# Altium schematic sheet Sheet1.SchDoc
size B
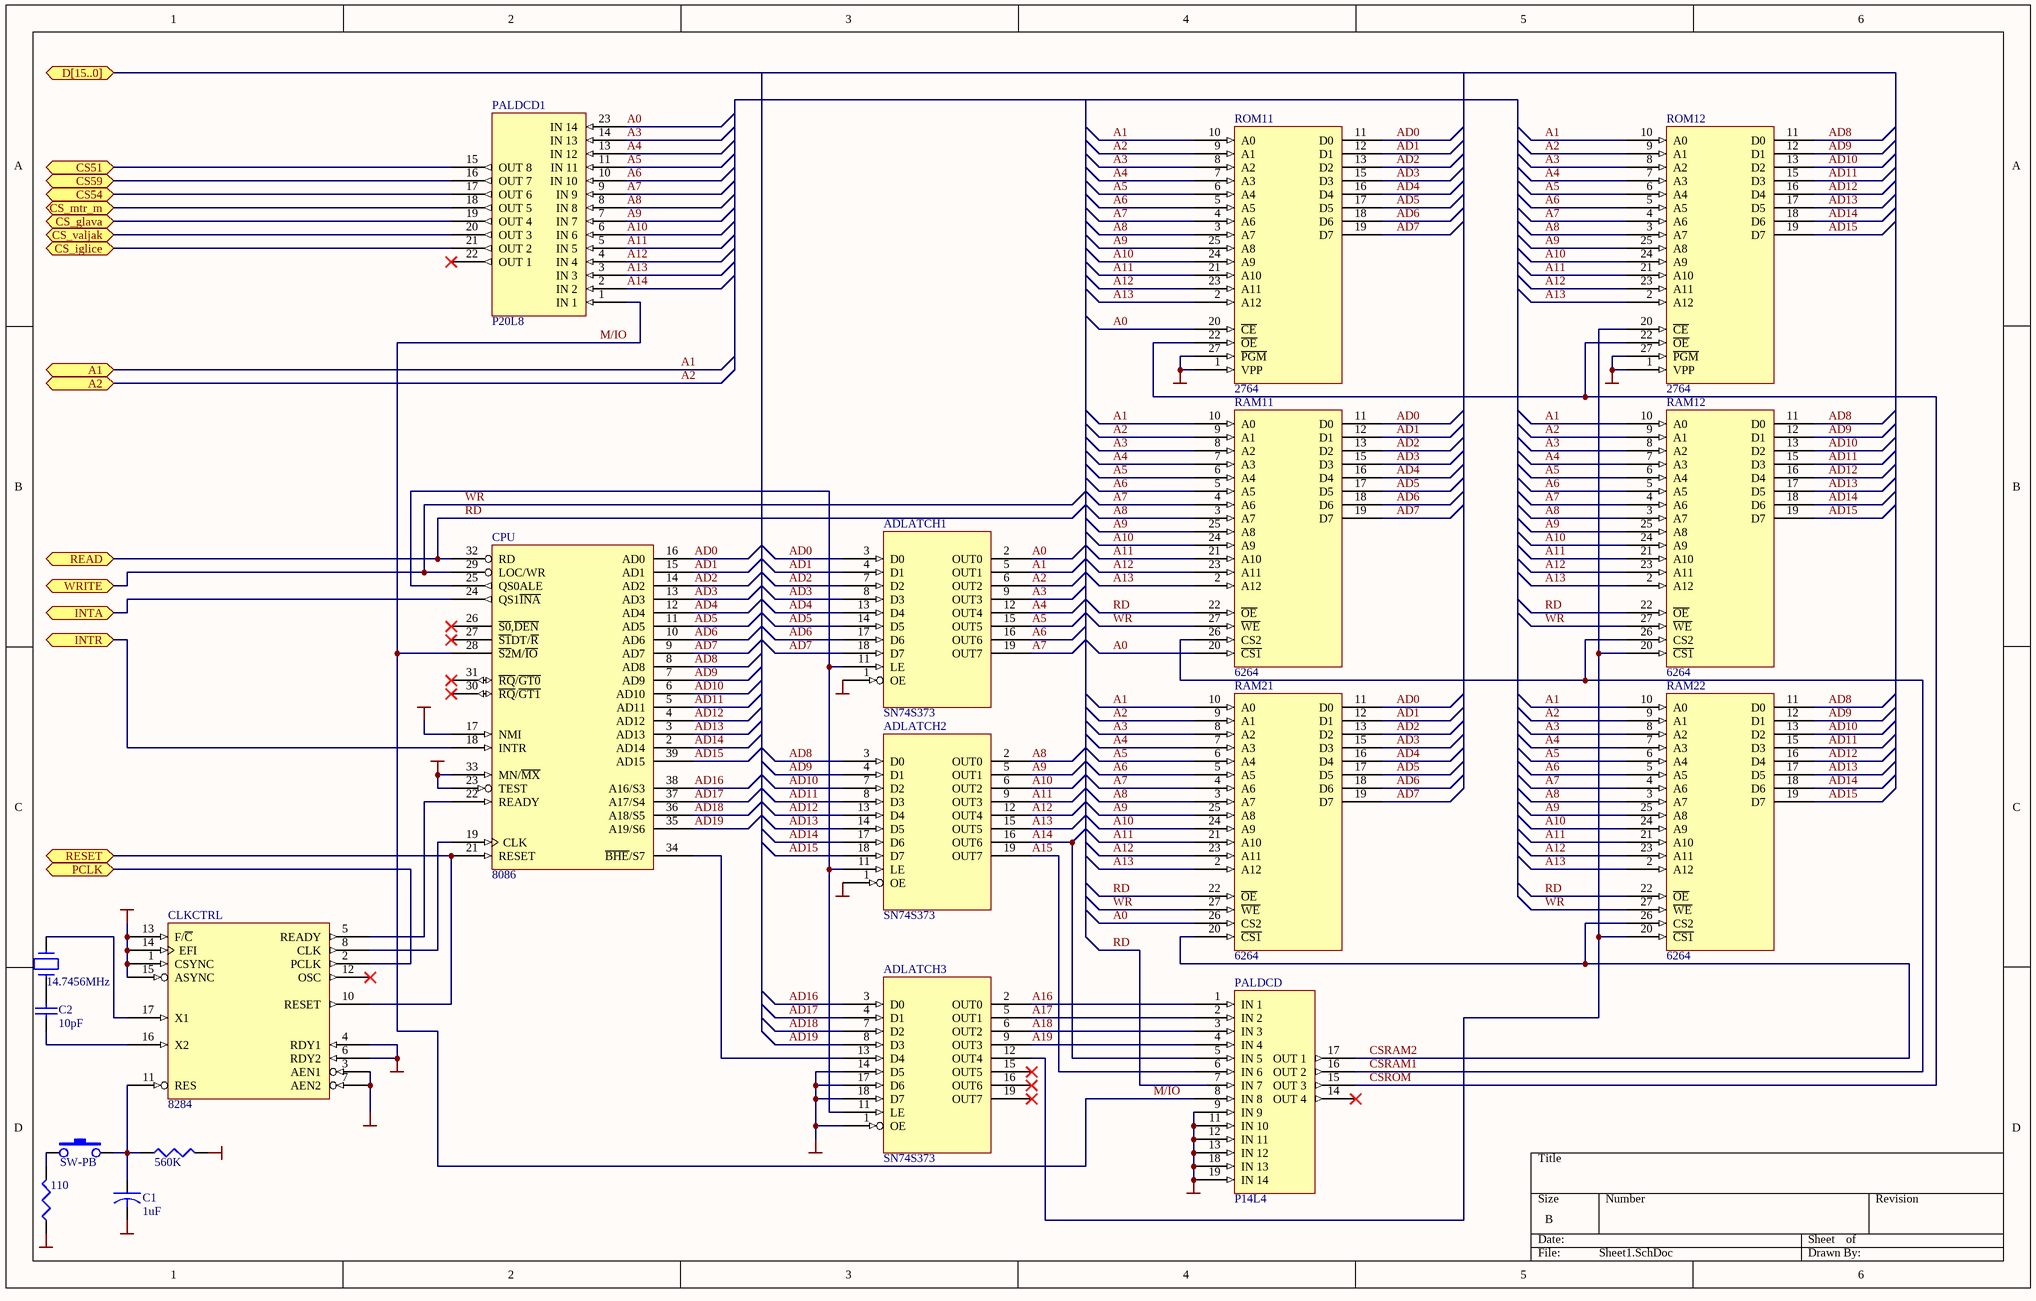
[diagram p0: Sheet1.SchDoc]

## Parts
(Parts that share a designator on the sheet are numbered #1, #2 ... from top to bottom, then left to right.)
?#1  14.7456MHz
?#2  SW-PB
?#3  560K
?#4  110
ADLATCH1  SN74S373
ADLATCH2  SN74S373
ADLATCH3  SN74S373
C1  1uF
C2  value 10pF  [C3216-1206]
CLKCTRL  8284  [DIP18]
CPU  8086  [DIP40]
PALDCD  P14L4  [DIP20]
PALDCD1  P20L8  [DIP24]
RAM11  6264  [DIP28]
RAM12  6264  [DIP28]
RAM21  6264  [DIP28]
RAM22  6264  [DIP28]
ROM11  2764  [DIP28]
ROM12  2764  [DIP28]

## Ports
A1, A2, CS51, CS54, CS59, CS_glava, CS_iglice, CS_mtr_m, CS_valjak, D[15..0], INTA, INTR, PCLK, READ, RESET, WRITE

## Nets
GND: ?#4.1 ADLATCH1.1(OE) ADLATCH2.1(OE) ADLATCH3.1(OE) ADLATCH3.14(D5) ADLATCH3.17(D6) ADLATCH3.18(D7) C1.2 CLKCTRL.1(CSYNC) CLKCTRL.3(AEN1) CLKCTRL.7(AEN2) CLKCTRL.9(GND) CLKCTRL.13(F/~{C}) CLKCTRL.14(EFI) CLKCTRL.15(ASYNC) CPU.1(GND) CPU.17(NMI) CPU.20(GND) PALDCD.9(IN_9) PALDCD.10(GND) PALDCD.11(IN_10) PALDCD.12(IN_11) PALDCD.13(IN_12) PALDCD.18(IN_13) PALDCD.19(IN_14) PALDCD1.12(GND) RAM11.14(GND) RAM12.14(GND) RAM21.14(GND) RAM22.14(GND) ROM11.14(GND) ROM12.14(GND)
VCC: ?#3.2 CLKCTRL.4(RDY1) CLKCTRL.6(RDY2) CLKCTRL.18(VCC) CPU.23(TEST) CPU.33(MN/~{MX}) CPU.40(VCC) PALDCD.20(VCC) PALDCD1.24(VCC) RAM11.28(VCC) RAM12.28(VCC) RAM21.28(VCC) RAM22.28(VCC) ROM11.1(VPP) ROM11.27(~{PGM}) ROM11.28(VCC) ROM12.1(VPP) ROM12.27(~{PGM}) ROM12.28(VCC)
A0: ADLATCH1.2(OUT0) PALDCD1.23(IN_14) RAM11.20(~{CS1}) RAM21.26(CS2) ROM11.20(~{CE})
A1: ADLATCH1.5(OUT1) RAM11.10(A0) RAM12.10(A0) RAM21.10(A0) RAM22.10(A0) ROM11.10(A0) ROM12.10(A0) ; port A1
A2: ADLATCH1.6(OUT2) RAM11.9(A1) RAM12.9(A1) RAM21.9(A1) RAM22.9(A1) ROM11.9(A1) ROM12.9(A1) ; port A2
A3: ADLATCH1.9(OUT3) PALDCD1.14(IN_13) RAM11.8(A2) RAM12.8(A2) RAM21.8(A2) RAM22.8(A2) ROM11.8(A2) ROM12.8(A2)
A4: ADLATCH1.12(OUT4) PALDCD1.13(IN_12) RAM11.7(A3) RAM12.7(A3) RAM21.7(A3) RAM22.7(A3) ROM11.7(A3) ROM12.7(A3)
A5: ADLATCH1.15(OUT5) PALDCD1.11(IN_11) RAM11.6(A4) RAM12.6(A4) RAM21.6(A4) RAM22.6(A4) ROM11.6(A4) ROM12.6(A4)
A6: ADLATCH1.16(OUT6) PALDCD1.10(IN_10) RAM11.5(A5) RAM12.5(A5) RAM21.5(A5) RAM22.5(A5) ROM11.5(A5) ROM12.5(A5)
A7: ADLATCH1.19(OUT7) PALDCD1.9(IN_9) RAM11.4(A6) RAM12.4(A6) RAM21.4(A6) RAM22.4(A6) ROM11.4(A6) ROM12.4(A6)
A8: ADLATCH2.2(OUT0) PALDCD1.8(IN_8) RAM11.3(A7) RAM12.3(A7) RAM21.3(A7) RAM22.3(A7) ROM11.3(A7) ROM12.3(A7)
A9: ADLATCH2.5(OUT1) PALDCD1.7(IN_7) RAM11.25(A8) RAM12.25(A8) RAM21.25(A8) RAM22.25(A8) ROM11.25(A8) ROM12.25(A8)
A10: ADLATCH2.6(OUT2) PALDCD1.6(IN_6) RAM11.24(A9) RAM12.24(A9) RAM21.24(A9) RAM22.24(A9) ROM11.24(A9) ROM12.24(A9)
A11: ADLATCH2.9(OUT3) PALDCD1.5(IN_5) RAM11.21(A10) RAM12.21(A10) RAM21.21(A10) RAM22.21(A10) ROM11.21(A10) ROM12.21(A10)
A12: ADLATCH2.12(OUT4) PALDCD1.4(IN_4) RAM11.23(A11) RAM12.23(A11) RAM21.23(A11) RAM22.23(A11) ROM11.23(A11) ROM12.23(A11)
A13: ADLATCH2.15(OUT5) PALDCD1.3(IN_3) RAM11.2(A12) RAM12.2(A12) RAM21.2(A12) RAM22.2(A12) ROM11.2(A12) ROM12.2(A12)
A14: ADLATCH2.16(OUT6) ADLATCH3.2(OUT0) ADLATCH3.5(OUT1) ADLATCH3.6(OUT2) ADLATCH3.9(OUT3) PALDCD.1(IN_1) PALDCD.2(IN_2) PALDCD.3(IN_3) PALDCD.4(IN_4) PALDCD.5(IN_5) PALDCD1.2(IN_2)  [also labelled A16, A17, A18, A19]
A15: ADLATCH2.19(OUT7) PALDCD.6(IN_6)
AD0: ADLATCH1.3(D0) CPU.16(AD0) RAM11.11(D0) RAM21.11(D0) ROM11.11(D0)
AD1: ADLATCH1.4(D1) CPU.15(AD1) RAM11.12(D1) RAM21.12(D1) ROM11.12(D1)
AD2: ADLATCH1.7(D2) CPU.14(AD2) RAM11.13(D2) RAM21.13(D2) ROM11.13(D2)
AD3: ADLATCH1.8(D3) CPU.13(AD3) RAM11.15(D3) RAM21.15(D3) ROM11.15(D3)
AD4: ADLATCH1.13(D4) CPU.12(AD4) RAM11.16(D4) RAM21.16(D4) ROM11.16(D4)
AD5: ADLATCH1.14(D5) CPU.11(AD5) RAM11.17(D5) RAM21.17(D5) ROM11.17(D5)
AD6: ADLATCH1.17(D6) CPU.10(AD6) RAM11.18(D6) RAM21.18(D6) ROM11.18(D6)
AD7: ADLATCH1.18(D7) CPU.9(AD7) RAM11.19(D7) RAM21.19(D7) ROM11.19(D7)
AD8: ADLATCH2.3(D0) CPU.8(AD8) RAM12.11(D0) RAM22.11(D0) ROM12.11(D0)
AD9: ADLATCH2.4(D1) CPU.7(AD9) RAM12.12(D1) RAM22.12(D1) ROM12.12(D1)
AD10: ADLATCH2.7(D2) CPU.6(AD10) RAM12.13(D2) RAM22.13(D2) ROM12.13(D2)
AD11: ADLATCH2.8(D3) CPU.5(AD11) RAM12.15(D3) RAM22.15(D3) ROM12.15(D3)
AD12: ADLATCH2.13(D4) CPU.4(AD12) RAM12.16(D4) RAM22.16(D4) ROM12.16(D4)
AD13: ADLATCH2.14(D5) CPU.3(AD13) RAM12.17(D5) RAM22.17(D5) ROM12.17(D5)
AD14: ADLATCH2.17(D6) CPU.2(AD14) RAM12.18(D6) RAM22.18(D6) ROM12.18(D6)
AD15: ADLATCH2.18(D7) CPU.39(AD15) RAM12.19(D7) RAM22.19(D7) ROM12.19(D7)
AD16: ADLATCH3.3(D0) CPU.38(A16/S3)
AD17: ADLATCH3.4(D1) CPU.37(A17/S4)
AD18: ADLATCH3.7(D2) CPU.36(A18/S5)
AD19: ADLATCH3.8(D3) CPU.35(A19/S6)
CS51: PALDCD1.15(OUT_8) ; port CS51
CS54: PALDCD1.17(OUT_6) ; port CS54
CS59: PALDCD1.16(OUT_7) ; port CS59
CS_glava: PALDCD1.19(OUT_4) ; port CS_glava
CS_iglice: PALDCD1.21(OUT_2) ; port CS_iglice
CS_mtr_m: PALDCD1.18(OUT_5) ; port CS_mtr_m
CS_valjak: PALDCD1.20(OUT_3) ; port CS_valjak
CSRAM1: PALDCD.16(OUT_2) RAM11.26(CS2) RAM12.26(CS2)
CSRAM2: PALDCD.17(OUT_1) RAM21.20(~{CS1}) RAM22.26(CS2)
CSROM: PALDCD.15(OUT_3) ROM11.22(~{OE}) ROM12.22(~{OE})
INTA: CPU.24(QS1~{INA}) ; port INTA
INTR: CPU.18(INTR) ; port INTR
M/IO: CLKCTRL.10(RESET) CPU.21(RESET) CPU.28(~{S2}M/~{IO}) PALDCD.8(IN_8) PALDCD1.1(IN_1) ; port RESET
PCLK: CLKCTRL.2(PCLK) ; port PCLK
RD: CPU.32(RD) PALDCD.7(IN_7) RAM11.22(~{OE}) RAM12.22(~{OE}) RAM21.22(~{OE}) RAM22.22(~{OE}) ; port READ
WR: CPU.29(LOC/WR) RAM11.27(~{WE}) RAM12.27(~{WE}) RAM21.27(~{WE}) RAM22.27(~{WE}) ; port WRITE
Net?#1_1: ?#1.1 C2.1
Net?#1_2: ?#1.2 CLKCTRL.17(X1)
Net?#2_1: ?#2.1 ?#4.2
Net?#2_2: ?#2.2 ?#3.1 C1.1 CLKCTRL.11(RES)
NetADLATCH1_11: ADLATCH1.11(LE) ADLATCH2.11(LE) ADLATCH3.11(LE) CPU.25(QS0ALE)
NetADLATCH3_12: ADLATCH3.12(OUT4) RAM12.20(~{CS1}) RAM22.20(~{CS1}) ROM12.20(~{CE})
NetADLATCH3_13: ADLATCH3.13(D4) CPU.34(~{BHE}/S7)
NetC2_2: C2.2 CLKCTRL.16(X2)
NetCLKCTRL_5: CLKCTRL.5(READY) CPU.22(READY)
NetCLKCTRL_8: CLKCTRL.8(CLK) CPU.19(CLK)

Not connected (* = marked no-connect by the designer): ADLATCH1 10(GND) 20(VCC); ADLATCH2 10(GND) 20(VCC); ADLATCH3 10(GND) 15(OUT5)* 16(OUT6)* 19(OUT7)* 20(VCC); CLKCTRL 12(OSC)*; CPU 26(~{S0},~{DEN})* 27(~{S1}DT/~{R})* 30(~{RQ}/~{GT1})* 31(~{RQ}/~{GT0})*; PALDCD 14(OUT_4)*; PALDCD1 22(OUT_1)*

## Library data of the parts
?#1 = CRYSTAL
?#3 ?#4 = RES1
C1 = CAPACITOR
C2 = Cap Semi: Capacitor (Semiconductor SIM Model); Manufacturer: Generic Components; Class I: Passive
PALDCD = P14L4: COMBINATORIAL LOGIC, WITH NO FEEDBACK 20-PIN PAL DEVICE
PALDCD1 = P20L8: 7.5ns 24-PIN TTL PAL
